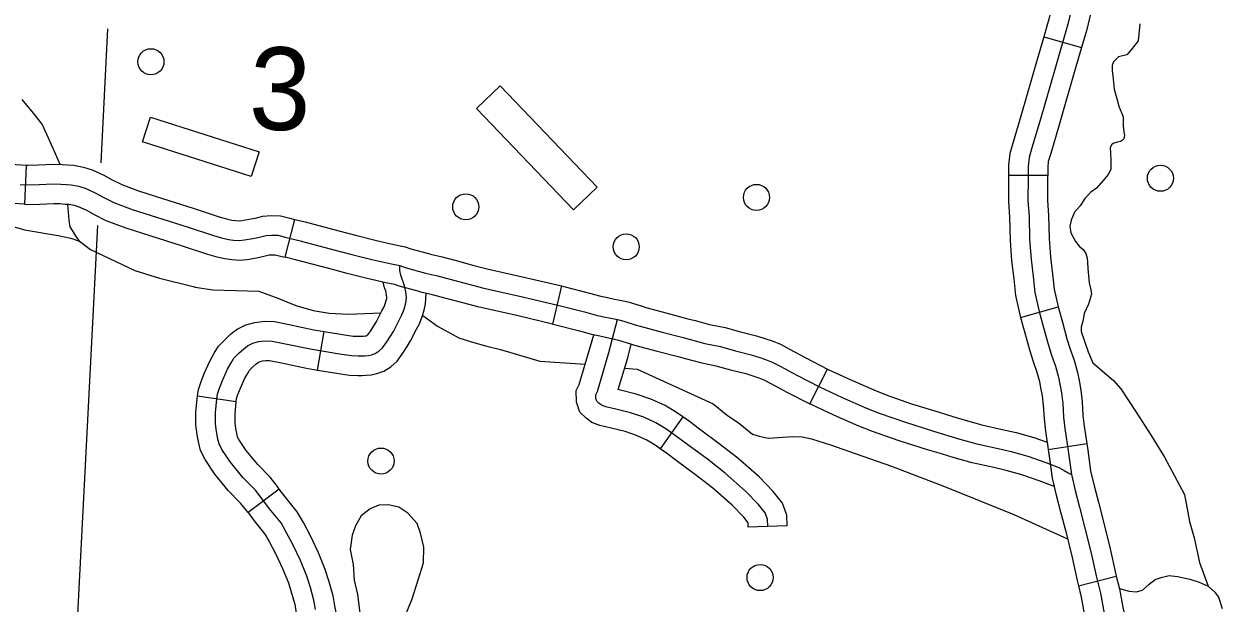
# Model space of a CAD drawing. Extents: x 653372 to 905732, y 627442 to 787275.
# Drawn here: x 699755 to 704351, y 749166 to 751385 of the extents above; entities that cross this region are included whole.
import ezdxf

# ---------------------------------------------------------------- set-up
doc = ezdxf.new("R2010")
doc.units = 0
for name, color, linetype in [('31', 7, 'Continuous'), ('32', 7, 'Continuous'), ('35', 7, 'Continuous'), ('5', 7, 'Continuous'), ('56', 7, 'Continuous'), ('57', 7, 'Continuous')]:
    doc.layers.add(name, color=color, linetype=linetype)

msp = doc.modelspace()

# ---------------------------------------------------------------- linework, layer by layer
at = {"layer": '31'}
for p, q in [((699764.1, 750844.3), (699756.8, 750694.5)), ((699756.8, 750694.5), (699756.8, 750694.5)), ((700757.1, 750491.1), (700794, 750636.5)), ((701817.3, 750381.2), (701782.5, 750235.3)), ((702769.6, 749929.2), (702837.9, 750062.8)), ((702837.9, 750062.8), (702837.9, 750062.8)), ((700734.5, 749603.1), (700614.8, 749512.7))]:
    msp.add_line(p, q, dxfattribs=at)
for points in [[(699252, 750949.4), (699255.3, 750949), (699313.4, 750939.7), (699353.6, 750931.4), (699375.6, 750926.3), (699399.5, 750921.1), (699448.3, 750909), (699503.9, 750895.3), (699558.1, 750882.7), (699617.8, 750867.7), (699662.3, 750856.8), (699693.4, 750851.1), (699723.9, 750846.8), (699745.1, 750845.2), (699764.1, 750844.3)], [(699764.1, 750844.3), (699770.8, 750844), (699810.5, 750844.8), (699867.9, 750847.6), (699901.3, 750846.6), (699922.4, 750844.8), (699945.2, 750843.9), (699984.1, 750836.5), (700017.3, 750826.1), (700061.1, 750805.8), (700094.1, 750788.3), (700130.1, 750769.8), (700195, 750745.4), (700286.8, 750716.3)], [(699756.8, 750694.5), (699735.8, 750695.5), (699707.8, 750697.6), (699669.4, 750703), (699631, 750710), (699581.6, 750722.1), (699522.7, 750736.9), (699469, 750749.5), (699412.4, 750763.3), (699365.5, 750775), (699342.5, 750780), (699321.4, 750784.9), (699286.4, 750792.1), (699235.3, 750800.3)], [(699740.5, 750770.3), (699769.8, 750768.9), (699813.1, 750769.8), (699868.6, 750772.5), (699897.1, 750771.7), (699917.9, 750770)], [(699917.9, 750770), (699936.6, 750769.2), (699965.8, 750763.7), (699990.2, 750756), (700027.8, 750738.6), (700059.4, 750721.8), (700099.6, 750701.1), (700170.4, 750674.5), (700380.9, 750607.7), (700481.9, 750574.5), (700513.2, 750565.2), (700539.1, 750559.8), (700559.5, 750556.8), (700581.8, 750555.7), (700601.3, 750557.4), (700632.6, 750563), (700658.8, 750568.2), (700683.6, 750574.5), (700705, 750576.2), (700729.2, 750575.4), (700756.9, 750568.6), (700815, 750553.8), (700943.9, 750520.2), (701013.1, 750501.8), (701089.2, 750482.8), (701158.5, 750466.7), (701197.1, 750459), (701217.1, 750452), (701295.9, 750430.7), (701341.2, 750419.6), (701393.3, 750406), (701462, 750387.6), (701514.2, 750374.4), (701667.5, 750339.8), (701807.8, 750306.3), (701904.7, 750281.5), (701950.3, 750269), (701979, 750263), (702005.8, 750257.6), (702032.1, 750252.4), (702055.9, 750246.3), (702100.1, 750232.9), (702119, 750226.8), (702202.9, 750204.2), (702283.2, 750183.2), (702367.3, 750161.2), (702427.4, 750148.7), (702484.1, 750132.5), (702545, 750117.7), (702577.7, 750106.9), (702599.8, 750099.8), (702625, 750089.7), (702655.7, 750073.4), (702719.3, 750039.2), (702807.2, 749994.2), (702893, 749954), (702986.6, 749913.5), (703035.9, 749894), (703136.2, 749858.9), (703243.4, 749825.5), (703344.8, 749794.6), (703410.7, 749775.8), (703491.8, 749758.5), (703542.1, 749747.2), (703605.7, 749728.6), (703675.2, 749705.1), (703724.8, 749685.9), (703744.9, 749674.6), (703760, 749665.3), (703772.8, 749659.4)], [(699756.8, 750694.5), (699768.7, 750693.9), (699815.7, 750694.8), (699869.3, 750697.5), (699892.9, 750696.8), (699913.3, 750695.1), (699928.1, 750694.5), (699947.4, 750690.8), (699963, 750685.9), (699994.4, 750671.4), (700024.6, 750655.3), (700069.2, 750632.4), (700145.9, 750603.6), (700241.4, 750573.3)], [(700286.8, 750716.3), (700404, 750679.1), (700504.3, 750646.1), (700531.7, 750637.9), (700552.2, 750633.6), (700566.8, 750631.5), (700580.3, 750630.8), (700591.3, 750631.8), (700618.6, 750636.7), (700642.2, 750641.4), (700671.4, 750648.8), (700703.2, 750651.2), (700739.5, 750650.2), (700775.1, 750641.3), (700794, 750636.5)], [(700794, 750636.5), (700833.7, 750626.4), (700963, 750592.7), (701031.8, 750574.4), (701106.8, 750555.7), (701174.3, 750540), (701217, 750531.5), (701239.3, 750523.6), (701306.4, 750505.6)], [(700241.4, 750573.3), (700357.8, 750536.4), (700459.5, 750502.9), (700494.8, 750492.4), (700526.1, 750485.9), (700552.2, 750482.1), (700583.2, 750480.5), (700611.2, 750483), (700646.5, 750489.3), (700675.3, 750495.1), (700695.7, 750500.2), (700706.8, 750501.1), (700718.9, 750500.7), (700738.6, 750495.8), (700757.1, 750491.1)], [(701306.4, 750505.6), (701314.6, 750503.4), (701359.6, 750492.3), (701412.5, 750478.5), (701480.9, 750460.2), (701531.6, 750447.4), (701684.4, 750412.9), (701817.3, 750381.2)], [(701267.5, 750360.7), (701194.9, 750380.3), (701177.2, 750386.5), (701142.6, 750393.4), (701071.7, 750409.8), (700994.4, 750429.2), (700924.8, 750447.6), (700796.3, 750481.2), (700757.1, 750491.1)], [(701817.3, 750381.2), (701825.8, 750379.1), (701923.9, 750354), (701968, 750342), (701994.1, 750336.5), (702020.5, 750331.1), (702048.7, 750325.6), (702076, 750318.6), (702122.6, 750304.5), (702140.3, 750298.7), (702222.1, 750276.7), (702302.2, 750255.8), (702329.9, 750248.5)], [(701782.5, 750235.3), (701650.5, 750266.8), (701496.7, 750301.5), (701443.2, 750315), (701374.1, 750333.5), (701322.7, 750346.9), (701277.3, 750358.1), (701267.5, 750360.7)], [(701782.5, 750235.3), (701789.8, 750233.5), (701885.5, 750209), (701932.7, 750196.1), (701963.9, 750189.6), (701991.1, 750184), (702015.6, 750179.2), (702035.7, 750174.1), (702077.6, 750161.4), (702097.6, 750154.8), (702183.7, 750131.7), (702264.2, 750110.7), (702291.8, 750103.4)], [(702329.9, 750248.5), (702384.5, 750234.2), (702445.3, 750221.5), (702503.2, 750205.1), (702565.6, 750189.9), (702601, 750178.2), (702625.3, 750170.4), (702656.6, 750157.9), (702691.1, 750139.6), (702754.2, 750105.6), (702837.9, 750062.8)], [(702291.8, 750103.4), (702350.1, 750088.1), (702409.4, 750075.8), (702464.9, 750060), (702524.4, 750045.5), (702554.4, 750035.7), (702574.3, 750029.2), (702593.5, 750021.5), (702620.4, 750007.3), (702684.5, 749972.8), (702769.6, 749929.2)], [(702837.9, 750062.8), (702840.2, 750061.6), (702923.8, 750022.4), (703015.3, 749982.8), (703062.1, 749964.3), (703159.8, 749930.1), (703265.5, 749897.2), (703318.7, 749880.9)], [(700614.8, 749512.7), (700608.3, 749521.2), (700586.2, 749549.6), (700538.9, 749597.8), (700487.8, 749660.6), (700449.8, 749716.2), (700432.3, 749750.4), (700425.9, 749778.7), (700419, 749811.2), (700414.9, 749848.6), (700414.8, 749898.8), (700420.8, 749960), (700569.2, 749938.3)], [(700873.2, 749141.9), (700867.4, 749177.8), (700853.8, 749226.2), (700840, 749269.8), (700815.7, 749328.9), (700786.7, 749390.1), (700761.4, 749438.2), (700741.2, 749473.1), (700697.6, 749527.5), (700667.9, 749566.8), (700642.8, 749599.1), (700594.9, 749647.9), (700547.9, 749705.5), (700514.4, 749754.6), (700503.4, 749776.2), (700499.2, 749794.8), (700493.2, 749823.1), (700489.9, 749852.7), (700489.8, 749895.3), (700495, 749949.2)], [(700734.5, 749603.1), (700727.4, 749612.4), (700699.4, 749648.5), (700650.8, 749697.9), (700608.1, 749750.4), (700579.1, 749792.9), (700574.5, 749801.9), (700572.4, 749810.9), (700567.3, 749835), (700564.9, 749856.9), (700564.9, 749891.7), (700569.2, 749938.3)], [(703274.9, 749737.5), (703221.3, 749753.8), (703112.7, 749787.7), (703009.7, 749823.7), (702957.9, 749844.2), (702862.1, 749885.6), (702774.2, 749926.9), (702769.6, 749929.3)], [(703318.7, 749880.9), (703366, 749866.5), (703428.8, 749848.7), (703507.8, 749831.8), (703560.9, 749819.9), (703628.3, 749800.1), (703679.4, 749782.8), (703699, 749645.4), (703707, 749612.4)], [(703707, 749612.4), (703649.7, 749634.6), (703583.1, 749657), (703523.3, 749674.6), (703475.7, 749685.2), (703392.6, 749703), (703323.6, 749722.6), (703274.9, 749737.5)], [(700959.4, 749097.4), (700947, 749155.7), (700940.8, 749193.9), (700925.7, 749247.6), (700910.6, 749295.4), (700884.4, 749359.2), (700853.8, 749423.6), (700827.1, 749474.5), (700803.3, 749515.6), (700756.8, 749573.5), (700734.5, 749603.1)], [(701190.2, 749075), (701196.9, 749085.6), (701213.2, 749107.5), (701243.8, 749182.6), (701269.1, 749258.9), (701287.4, 749321), (701289.2, 749379.8), (701276.2, 749434.3), (701263, 749471), (701228.2, 749510.6), (701192.8, 749533.7), (701152.8, 749542.6), (701116.6, 749541.7), (701083.1, 749527.1), (701048.2, 749500.6), (701027.4, 749461.9), (701013.5, 749425.9), (701006.6, 749370.9), (701017.4, 749314.3), (701022.2, 749254.6), (701034.4, 749198.9), (701045.1, 749118.9)], [(700614.8, 749512.7), (700638.4, 749481.4), (700679.2, 749430.6), (700695.8, 749401.9), (700719.6, 749356.6), (700747.1, 749298.5), (700769.5, 749244.2), (700781.9, 749204.7), (700794.1, 749161.6), (700799.5, 749128.1), (700812.8, 749066)]]:
    msp.add_lwpolyline(points, dxfattribs=at)
at = {"layer": '32'}
for p, q in [((703667.1, 751336.1), (703811.2, 751294.5)), ((703531.9, 750806.1), (703681.9, 750805.7)), ((703577.3, 750260.9), (703721.8, 750301.1)), ((700881, 750059.2), (700906.3, 750207)), ((702282.1, 749879.6), (702195.7, 749757)), ((703683.5, 749755.2), (703831.9, 749777.2)), ((702683, 749461.7), (702533.1, 749457.4)), ((703799.5, 749232.9), (703944.9, 749269.6))]:
    msp.add_line(p, q, dxfattribs=at)
for points in [[(703893.5, 751840), (703844.1, 751789), (703807.1, 751750.5), (703778.5, 751711), (703762.4, 751672.1), (703746.1, 751626.4), (703724.6, 751554.6), (703703.3, 751470.6), (703686.6, 751403.3), (703667.1, 751336.1)], [(704001.3, 751735.6), (703952.1, 751684.9), (703922.6, 751654.1), (703910.4, 751637.3), (703902.4, 751618.1), (703888.6, 751579.6), (703869.2, 751514.6), (703848.8, 751434.1), (703831.5, 751364.4), (703811.2, 751294.5)], [(703776, 751452.4), (703759, 751383.9), (703711.5, 751219.6), (703653.8, 751020), (703621.7, 750910.1), (703610.3, 750873.7), (703607, 750840.4), (703606.9, 750797.8), (703606.4, 750707), (703610.4, 750648.2), (703612.3, 750559.5), (703618.1, 750484.5), (703626.5, 750417.6), (703632.7, 750356.4), (703648.9, 750283.4), (703666, 750221.9), (703683.7, 750158.1), (703696.8, 750115.7), (703711.6, 750073.9), (703723, 750032.1), (703728.5, 750004.9), (703734.4, 749971.4), (703739.5, 749930.9), (703742.6, 749878.9), (703747.6, 749834.5), (703761.4, 749740.9), (703772.8, 749659.4), (703787.6, 749598), (703803.5, 749534.2), (703823.7, 749458.9), (703848.8, 749357.4), (703867.5, 749270), (703883.9, 749204.8), (703898.3, 749126.7)], [(703667.1, 751336.1), (703639.5, 751240.4), (703581.8, 751040.9), (703549.9, 750931.9), (703536.4, 750888.8), (703532, 750844.2), (703531.9, 750806.1)], [(703811.2, 751294.5), (703783.6, 751198.8), (703725.8, 750999.1), (703693.5, 750888.4), (703684.1, 750858.6), (703682, 750836.6), (703681.9, 750805.7)], [(703531.9, 750806.1), (703531.9, 750798.1), (703531.4, 750704.6), (703535.5, 750644.8), (703537.4, 750555.8), (703543.5, 750477), (703552, 750409.1), (703558.5, 750344.4), (703576.1, 750265.2), (703577.3, 750260.9)], [(703681.9, 750805.7), (703681.8, 750797.5), (703681.4, 750709.3), (703685.4, 750651.5), (703687.3, 750563.2), (703692.8, 750492.1), (703701, 750426), (703706.9, 750368.4), (703721.7, 750301.6), (703721.8, 750301.1)], [(700495, 749949.2), (700497.6, 749966.9), (700505.2, 749990), (700516.3, 750019.2), (700536.1, 750061.8), (700549.9, 750086.1), (700560.7, 750104.3), (700581.2, 750124.9), (700596.8, 750139.6), (700612.9, 750151.4), (700633.1, 750161.8), (700655.2, 750168), (700680.7, 750171.4), (700706.7, 750169.9), (700758.1, 750160), (700853.5, 750140), (700965.4, 750120.8), (701011.2, 750114.7), (701036.5, 750113.2), (701050.3, 750113.5), (701062.6, 750113.8), (701076.4, 750115.4), (701088.8, 750117.8), (701102.7, 750122.9), (701117.3, 750132.1), (701130.7, 750144), (701147.2, 750166.8), (701161.6, 750188.4), (701172.4, 750207.2), (701194.3, 750250.5), (701205.2, 750270.1), (701213.4, 750291.8), (701217.9, 750306.7), (701221.2, 750323.1), (701222.3, 750339.5), (701219.5, 750358.8), (701215.4, 750382.3), (701200.8, 750422.5), (701197.3, 750441.1), (701197.1, 750459)], [(700906.3, 750207), (700976.8, 750195), (701018.4, 750189.4), (701037.9, 750188.3), (701048.6, 750188.5), (701057.2, 750188.7), (701064.9, 750189.6), (701068.8, 750190.3), (701069.6, 750190.6), (701072.2, 750192.3), (701074.7, 750194.5), (701085.6, 750209.6), (701097.8, 750227.9), (701106.4, 750242.9), (701128, 750285.6), (701136.9, 750301.7), (701142.3, 750316), (701145.1, 750325), (701146.7, 750333.1), (701146.9, 750336.7), (701145.4, 750346.9), (701142.6, 750362.9), (701138.4, 750374.6), (701132.7, 750395.7)], [(700881, 750059.2), (700954.1, 750046.7), (701004, 750039.9), (701035.2, 750038.2), (701052, 750038.5), (701068, 750038.9), (701087.9, 750041.3), (701108.9, 750045.3), (701135.8, 750055.1), (701162.5, 750071.8), (701186.8, 750093.5), (701208.8, 750124.1), (701225.3, 750148.8), (701238.4, 750171.6), (701260.6, 750215.3), (701273.4, 750238.4), (701284.4, 750267.5), (701290.8, 750288.5), (701295.6, 750313.1), (701298.5, 750352.9)], [(703721.8, 750301.1), (703738.3, 750242), (703755.7, 750179.2), (703768, 750139.3), (703783.3, 750096.3), (703796, 750049.4), (703802.2, 750018.8), (703808.6, 749982.6), (703814.3, 749937.8), (703817.3, 749885.3), (703822, 749844.2), (703831.9, 749777.2)], [(700420.8, 749960), (700424.3, 749984.1), (700434.5, 750015.1), (700447.2, 750048.4), (700469.4, 750096.1), (700485, 750123.8), (700501, 750150.6), (700528.9, 750178.7), (700548.6, 750197.3), (700573.3, 750215.4), (700605.6, 750232), (700640.1, 750241.7), (700677.9, 750246.6), (700716, 750244.5), (700772.9, 750233.5), (700867.6, 750213.7), (700906.3, 750207)], [(702608.1, 749459.5), (702607.2, 749488.3), (702598.6, 749511.4), (702572.6, 749544.3), (702523.4, 749595.6), (702445.2, 749663.9), (702376.9, 749717.2), (702301.7, 749772.7), (702263.7, 749800.8), (702217.3, 749833.5), (702179.1, 749856.6), (702132.5, 749878.3), (702082.3, 749895), (702025.2, 749909.4), (701986.6, 749918.2), (701970.8, 749924.6), (701960, 749932.5), (701952.6, 749939.5), (701948.7, 749950.6), (701948.3, 749964.1), (701954.6, 749976.6), (701998.8, 750126.6), (702032.1, 750252.4)], [(703577.3, 750260.9), (703593.8, 750201.9), (703611.7, 750137), (703625.6, 750092.1), (703640, 750051.4), (703650, 750014.8), (703654.8, 749991), (703660.3, 749960.1), (703664.8, 749924), (703667.8, 749872.6), (703673.2, 749824.8), (703683.5, 749755.2)], [(702195.7, 749757), (702176.2, 749770.7), (702143.8, 749790.3), (702104.7, 749808.5), (702061.2, 749823), (702007.7, 749836.5), (701964.2, 749846.4), (701933.9, 749858.5), (701911.8, 749874.8), (701887.9, 749897.5), (701874.1, 749936.6), (701872.7, 749980.8), (701884.5, 750004.3), (701940.5, 750194)], [(702282.1, 749879.6), (702258.4, 749896.3), (702214.5, 749922.9), (702160.2, 749948.1), (702103.3, 749967), (702042.7, 749982.3), (702035, 749984.1), (702071, 750106.4), (702084.8, 750158.3)], [(700569.2, 749938.3), (700570.9, 749949.7), (700575.9, 749964.9), (700585.4, 749989.9), (700602.9, 750027.5), (700614.7, 750048.4), (700620.4, 750058), (700633.6, 750071.2), (700644.9, 750081.9), (700652.5, 750087.5), (700660.6, 750091.6), (700670.3, 750094.3), (700683.5, 750096.1), (700697.5, 750095.3), (700743.3, 750086.5), (700839.5, 750066.3), (700881, 750059.2)], [(702683, 749461.7), (702681.9, 749502.9), (702664.8, 749548.7), (702629.2, 749593.6), (702575.3, 749649.9), (702493, 749721.8), (702422.3, 749776.9), (702346.2, 749833.1), (702307.5, 749861.6), (702282.1, 749879.6)], [(703831.9, 749777.2), (703835.7, 749751.6), (703846.6, 749673.4), (703860.5, 749615.9), (703876.2, 749553), (703896.3, 749477.6), (703921.9, 749374.3), (703940.6, 749287), (703944.9, 749269.6)], [(702533.1, 749457.4), (702532.6, 749473.7), (702532.5, 749474.1), (702516, 749495), (702471.6, 749541.3), (702397.4, 749606.1), (702331.6, 749657.4), (702257.1, 749712.4), (702219.8, 749740), (702195.7, 749757)], [(703683.5, 749755.2), (703687.2, 749730.2), (703699, 749645.4), (703714.8, 749580.1), (703730.9, 749515.5), (703751.1, 749440.1), (703775.7, 749340.6), (703794.4, 749253), (703799.5, 749232.9)], [(703944.9, 749269.6), (703957.3, 749220.8), (703971.6, 749142.7), (703989.2, 749072.9), (704000.7, 749022.4), (704006.2, 748958), (704011.1, 748911.3), (704013.9, 748878.8), (704015.5, 748813.7), (704021.3, 748735.9)], [(703799.5, 749232.9), (703810.6, 749188.9), (703825, 749110.8), (703843.3, 749037.9), (703852.1, 748999.3), (703856.9, 748943.8), (703861.8, 748896.9), (703864.1, 748870.6), (703865.6, 748806.3), (703871.8, 748724.6)]]:
    msp.add_lwpolyline(points, dxfattribs=at)
at = {"layer": '35'}
for points in [[(704035.9, 751385.8), (704028.4, 751320.1), (704002.1, 751285.9), (703986.1, 751266.7), (703954.1, 751258.9)], [(703954.1, 751258.9), (703934.9, 751239.8), (703928.9, 751226), (703929.7, 751204.9), (703931.2, 751186.6), (703937.4, 751135.6), (703948.1, 751094.7), (703955, 751069.9), (703972, 751028.8), (703971, 750995.2), (703974.5, 750971.2), (703976.9, 750957.8), (703973.7, 750945.3), (703967.9, 750939.2), (703960.8, 750935.2), (703950.2, 750932.7), (703936.1, 750928.9), (703927.5, 750922.9), (703921.6, 750911.8), (703923.7, 750865.5), (703923.9, 750827), (703913.5, 750807.7), (703895.3, 750785.1), (703869.2, 750755.8), (703847.1, 750741.1), (703823.9, 750716.6), (703807, 750688.4), (703784.5, 750664.5), (703771.7, 750633.2), (703766.8, 750610.2), (703770.2, 750584.9), (703788.1, 750551.4), (703803, 750533.4), (703818.1, 750521.1), (703828.8, 750506), (703833.2, 750487.7), (703834.8, 750472.2), (703836.2, 750447.6), (703838.8, 750419.5), (703840.8, 750393.5), (703847, 750366), (703849.7, 750349.5)], [(699893.9, 750847.2), (699867.5, 750907.7), (699825.6, 751001.3), (699792.2, 751042.7), (699747.7, 751095.9)], [(699968.7, 750552.9), (699956.7, 750569.4), (699932.9, 750607.5), (699928, 750633.6), (699923.2, 750694.3)], [(699468.1, 750675.5), (699740, 750600.8), (699757, 750596.4), (699885.9, 750574.6), (699935.2, 750563.8), (699968.7, 750552.9), (700010.8, 750521), (700180.2, 750440.9), (700275.3, 750410.9), (700404.3, 750379.7)], [(700404.3, 750379.7), (700411.5, 750377), (700480.2, 750366.4), (700655.8, 750361.3), (700729.1, 750334.6), (700798.1, 750305.9), (700864.2, 750287.3), (700925.4, 750277), (700999.5, 750273.7), (701124.2, 750278.2)], [(703849.7, 750349.5), (703838.7, 750311.4), (703822.1, 750276.2), (703816.4, 750246.2), (703810.8, 750223.2), (703810.3, 750207.3), (703837.2, 750128.5), (703855.1, 750086.9), (703933.8, 750018.4), (703962.3, 749986.9)], [(701284.6, 750268), (701341.9, 750227.2), (701423.4, 750182.1), (701475.3, 750166), (701530.6, 750150), (701583.3, 750137.8), (701733.6, 750093.7), (701907.2, 750081.2)], [(702059.1, 750065.9), (702107.2, 750061.8), (702399, 749929.7), (702453.7, 749885.4), (702494.3, 749858.6), (702550.1, 749813.7), (702574.9, 749806.1), (702610, 749798.6), (702704.3, 749805), (702740.8, 749803.3), (702776.5, 749795.5), (702848.8, 749772.6), (702944, 749738.7), (703082.9, 749690.4), (703285.7, 749612.5), (703551.8, 749505.2), (703757.8, 749412.9)], [(703962.3, 749986.9), (704020.9, 749898.1), (704078.4, 749808.5), (704129.6, 749725.6), (704206.6, 749581.7), (704226.3, 749478.7), (704243.9, 749416.3), (704263.9, 749321.3), (704298, 749230.5)], [(703957, 749222.2), (703994.1, 749211.3), (704020.9, 749209), (704045, 749215.7), (704071.1, 749238.8), (704094, 749256.1), (704116.7, 749264.4), (704148.3, 749272.4), (704179.6, 749268.5), (704227.1, 749258.1), (704262.6, 749246.5), (704298, 749230.5), (704322.7, 749207.6), (704337.2, 749188.6), (704350.7, 749145.5)]]:
    msp.add_lwpolyline(points, dxfattribs=at)
at = {"layer": '5'}
for points in [[(700076, 751365.9), (700049.7, 750853.6)], [(700037.3, 750613.3), (699912.4, 748178.7)]]:
    msp.add_lwpolyline(points, dxfattribs=at)
at = {"layer": '56'}
msp.add_lwpolyline([(700209.9, 750933.2), (700240.3, 751028.5), (700657.1, 750895.7), (700626.8, 750800.4)], close=True, dxfattribs=at)
for centre in [(700242.2, 751240.2), (704114.3, 750794), (701449.7, 750684.5), (702564.9, 750720.6), (702065.3, 750531.2), (701124.7, 749710.3), (702578.7, 749264)]:
    msp.add_circle(centre, 50, dxfattribs=at)
at = {"layer": '57'}
for p, q in [((701581.8, 751147.8), (701491.6, 751061.4)), ((701953.6, 750759.6), (701581.8, 751147.8)), ((701491.6, 751061.4), (701863.3, 750673.2)), ((701863.3, 750673.2), (701953.6, 750759.6))]:
    msp.add_line(p, q, dxfattribs=at)

# ---------------------------------------------------------------- texts
at = {"layer": '56'}
msp.add_text('3', height=316.8, rotation=358.28, dxfattribs=at).set_placement((700615.5, 750982.4))

doc.saveas('drawing.dxf')
